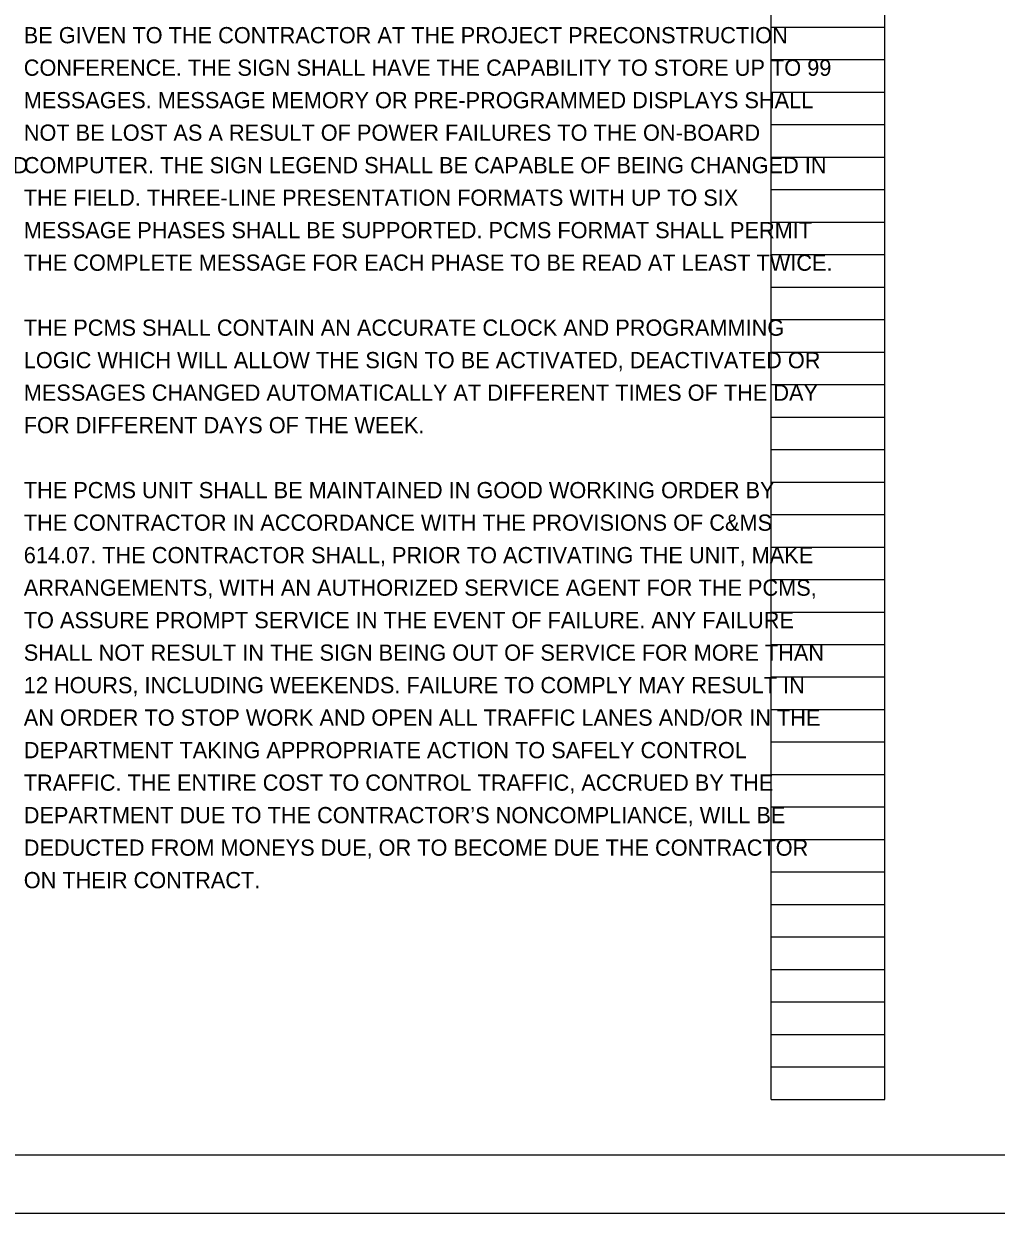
# Model space of a CAD drawing. Extents: x -19 to 34, y 0 to 22.
# Drawn here: x 17.24 to 25.62, y 0 to 10.25 of the extents above; entities that cross this region are included whole.
import ezdxf

# ---------------------------------------------------------------- set-up
doc = ezdxf.new("R2010")
doc.units = 0
for name, color, linetype in [('SH_Border', 7, 'Continuous'), ('SH_Cut_Line', 7, 'Continuous'), ('SH_Data', 7, 'Continuous'), ('SH_Text', 7, 'Continuous')]:
    doc.layers.add(name, color=color, linetype=linetype)

msp = doc.modelspace()

# ---------------------------------------------------------------- linework, layer by layer
at = {"layer": 'SH_Border'}
msp.add_lwpolyline([(1.5, 21.5), (33.5, 21.5), (33.5, 0.5), (1.5, 0.5)], close=True, dxfattribs=at)
at = {"layer": 'SH_Cut_Line'}
msp.add_lwpolyline([(0, 0), (34, 0), (34, 22), (0, 22)], close=True, dxfattribs=at)
at = {"layer": 'SH_Data'}
for p, q in [((23.68, 0.98), (23.68, 21.14)), ((24.66, 0.98), (24.66, 21.14)), ((23.68, 10.22), (24.66, 10.22)), ((23.68, 9.94), (24.66, 9.94)), ((23.68, 9.66), (24.66, 9.66)), ((23.68, 9.38), (24.66, 9.38)), ((23.68, 9.1), (24.66, 9.1)), ((23.68, 8.82), (24.66, 8.82)), ((23.68, 8.54), (24.66, 8.54)), ((23.68, 8.26), (24.66, 8.26)), ((23.68, 7.98), (24.66, 7.98)), ((23.68, 7.7), (24.66, 7.7)), ((23.68, 7.42), (24.66, 7.42)), ((23.68, 7.14), (24.66, 7.14)), ((23.68, 6.86), (24.66, 6.86)), ((23.68, 6.58), (24.66, 6.58)), ((23.68, 6.3), (24.66, 6.3)), ((23.68, 6.02), (24.66, 6.02)), ((23.68, 5.74), (24.66, 5.74)), ((23.68, 5.46), (24.66, 5.46)), ((23.68, 5.18), (24.66, 5.18)), ((23.68, 4.9), (24.66, 4.9)), ((23.68, 4.62), (24.66, 4.62)), ((23.68, 4.34), (24.66, 4.34)), ((23.68, 4.06), (24.66, 4.06)), ((23.68, 3.78), (24.66, 3.78)), ((23.68, 3.5), (24.66, 3.5)), ((23.68, 3.22), (24.66, 3.22)), ((23.68, 2.94), (24.66, 2.94)), ((23.68, 2.66), (24.66, 2.66)), ((23.68, 2.38), (24.66, 2.38)), ((23.68, 2.1), (24.66, 2.1)), ((23.68, 1.82), (24.66, 1.82)), ((23.68, 1.54), (24.66, 1.54)), ((23.68, 1.26), (24.66, 1.26)), ((23.68, 0.98), (24.66, 0.98))]:
    msp.add_line(p, q, dxfattribs=at)

# ---------------------------------------------------------------- texts
at = {"layer": 'SH_Text'}
for s, p in [('BE GIVEN TO THE CONTRACTOR AT THE PROJECT PRECONSTRUCTION ', (17.24, 10.08)), ('CONFERENCE. THE SIGN SHALL HAVE THE CAPABILITY TO STORE UP TO 99 ', (17.24, 9.8)), ('MESSAGES. MESSAGE MEMORY OR PRE-PROGRAMMED DISPLAYS SHALL ', (17.24, 9.52)), ('NOT BE LOST AS A RESULT OF POWER FAILURES TO THE ON-BOARD ', (17.24, 9.24)), ('PHYSICALLY POSSIBLE. THE FIRST SIGN SHALL BE PLACED BETWEEN THE ROAD ', (9.82, 8.96)), ('COMPUTER. THE SIGN LEGEND SHALL BE CAPABLE OF BEING CHANGED IN ', (17.24, 8.96)), ('THE FIELD. THREE-LINE PRESENTATION FORMATS WITH UP TO SIX ', (17.24, 8.68)), ('MESSAGE PHASES SHALL BE SUPPORTED. PCMS FORMAT SHALL PERMIT ', (17.24, 8.4)), ('THE COMPLETE MESSAGE FOR EACH PHASE TO BE READ AT LEAST TWICE.', (17.24, 8.12)), ('THE PCMS SHALL CONTAIN AN ACCURATE CLOCK AND PROGRAMMING ', (17.24, 7.56)), ('LOGIC WHICH WILL ALLOW THE SIGN TO BE ACTIVATED, DEACTIVATED OR ', (17.24, 7.28)), ('MESSAGES CHANGED AUTOMATICALLY AT DIFFERENT TIMES OF THE DAY ', (17.24, 7)), ('FOR DIFFERENT DAYS OF THE WEEK.', (17.24, 6.72)), ('THE PCMS UNIT SHALL BE MAINTAINED IN GOOD WORKING ORDER BY ', (17.24, 6.16)), ('THE CONTRACTOR IN ACCORDANCE WITH THE PROVISIONS OF C&MS ', (17.24, 5.88)), ('614.07. THE CONTRACTOR SHALL, PRIOR TO ACTIVATING THE UNIT, MAKE ', (17.24, 5.6)), ('ARRANGEMENTS, WITH AN AUTHORIZED SERVICE AGENT FOR THE PCMS, ', (17.24, 5.32)), ('TO ASSURE PROMPT SERVICE IN THE EVENT OF FAILURE. ANY FAILURE ', (17.24, 5.04)), ('SHALL NOT RESULT IN THE SIGN BEING OUT OF SERVICE FOR MORE THAN ', (17.24, 4.76)), ('12 HOURS, INCLUDING WEEKENDS. FAILURE TO COMPLY MAY RESULT IN ', (17.24, 4.48)), ('AN ORDER TO STOP WORK AND OPEN ALL TRAFFIC LANES AND/OR IN THE ', (17.24, 4.2)), ('DEPARTMENT TAKING APPROPRIATE ACTION TO SAFELY CONTROL ', (17.24, 3.92)), ('TRAFFIC. THE ENTIRE COST TO CONTROL TRAFFIC, ACCRUED BY THE ', (17.24, 3.64)), ('DEPARTMENT DUE TO THE CONTRACTOR’S NONCOMPLIANCE, WILL BE ', (17.24, 3.36)), ('DEDUCTED FROM MONEYS DUE, OR TO BECOME DUE THE CONTRACTOR ', (17.24, 3.08)), ('ON THEIR CONTRACT. ', (17.24, 2.8))]:
    msp.add_text(s, height=0.14, dxfattribs=at).set_placement(p)

doc.saveas('drawing.dxf')
